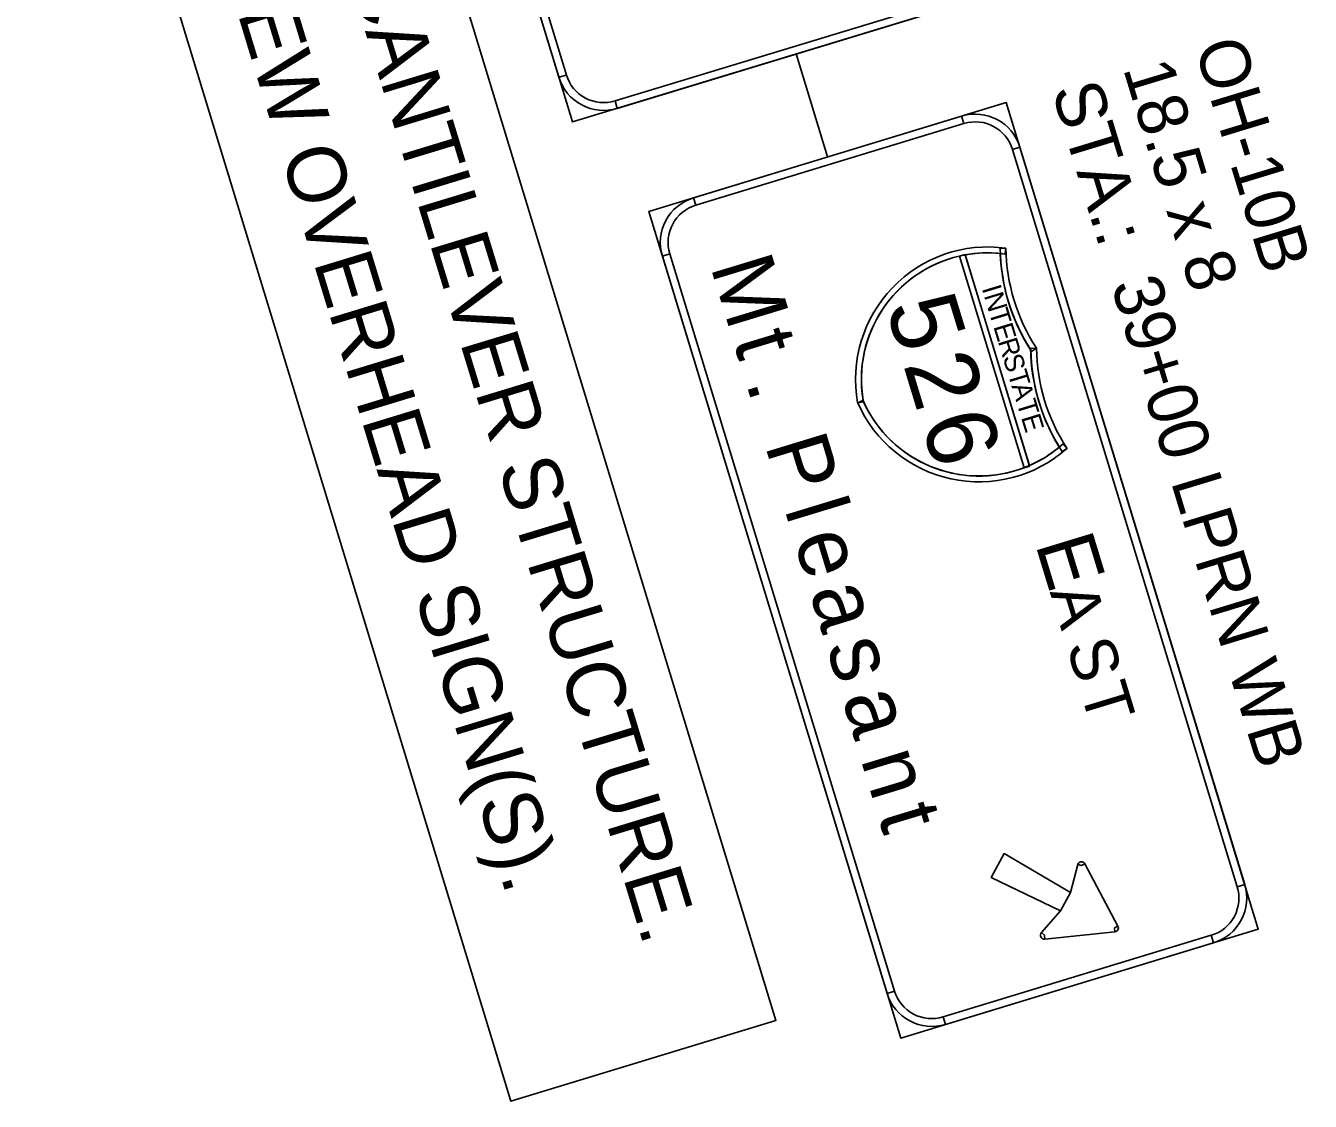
# Model space of a CAD drawing. Extents: x 2338610 to 2351914, y 366540 to 376484.
# Drawn here: x 2348805.7 to 2349063.5, y 367290.3 to 367506.3 of the extents above; entities that cross this region are included whole.
import ezdxf

# ---------------------------------------------------------------- set-up
doc = ezdxf.new("R2010")
doc.units = 0
doc.layers.add('TR PM UNASSIGNED 3', color=7, linetype='Continuous')
doc.layers.add('TR SN EXTRUDED PANEL SIGNS- MOUNTED OVERHEAD', color=7, linetype='Continuous')

msp = doc.modelspace()

# ---------------------------------------------------------------- linework, layer by layer
at = {"layer": 'TR SN EXTRUDED PANEL SIGNS- MOUNTED OVERHEAD'}
for p, q in [((2348966.6, 367479.94), (2348960.3, 367500.64)), ((2348914.19, 367496.4), (2348912.7, 367495.95)), ((2348924.41, 367489.71), (2348923.95, 367491.2)), ((2348993.52, 367488.14), (2348993.98, 367486.65)), ((2349003.73, 367481.45), (2349005.23, 367481.91)), ((2348940.14, 367470.25), (2348939.69, 367471.74)), ((2348933.45, 367460.03), (2348934.94, 367460.49)), ((2349007.13, 367417.99), (2348994.25, 367460.29)), ((2349002.42, 367461.62), (2349001.25, 367461.61)), ((2349002.26, 367460.46), (2349002.42, 367461.62)), ((2348993.09, 367460.05), (2349006.04, 367417.54)), ((2349008.54, 367441.53), (2349007.37, 367441.51)), ((2349007.56, 367440.89), (2349008.54, 367441.53)), ((2348973.72, 367431.06), (2348972.65, 367430.59)), ((2348972.65, 367430.59), (2348973.81, 367430.8)), ((2349014.67, 367421.43), (2349013.89, 367422.31)), ((2349013.68, 367420.79), (2349014.67, 367421.43)), ((2349016.82, 367337.83), (2349017.57, 367337.63)), ((2349017.57, 367337.63), (2349018.26, 367338)), ((2349050.34, 367333.85), (2349048.84, 367333.4)), ((2349010.13, 367323.66), (2349009.54, 367324.18)), ((2349010.21, 367322.88), (2349010.13, 367323.66)), ((2349024.89, 367325.5), (2349024.2, 367325.13)), ((2349024.2, 367325.13), (2349024.28, 367324.35)), ((2349043.64, 367323.64), (2349044.1, 367322.15)), ((2348980.05, 367312.44), (2348978.56, 367311.98)), ((2348990.26, 367305.74), (2348989.81, 367307.24))]:
    msp.add_line(p, q, dxfattribs=at)
for points in [[(2348868.96, 367639.51), (2348915.43, 367486.97), (2349005.16, 367514.31), (2348958.68, 367666.85), (2348868.96, 367639.51), (2348868.96, 367639.51)], [(2348873.19, 367630.99), (2348914.19, 367496.4), (2348912.7, 367495.95), (2348871.69, 367630.54), (2348873.19, 367630.99), (2348873.19, 367630.99)], [(2348858.9, 367626.03), (2348956.25, 367306.52), (2348903.01, 367290.3), (2348805.66, 367609.81)], [(2348923.95, 367491.2), (2348995.73, 367513.07), (2348996.19, 367511.58), (2348924.41, 367489.71), (2348923.95, 367491.2), (2348923.95, 367491.2)], [(2348930.71, 367469.01), (2348981.29, 367303.01), (2349053.07, 367324.88), (2349002.49, 367490.88), (2348930.71, 367469.01), (2348930.71, 367469.01)], [(2348993.98, 367486.65), (2348940.14, 367470.25), (2348939.69, 367471.74), (2348993.52, 367488.14), (2348993.98, 367486.65), (2348993.98, 367486.65)], [(2349048.84, 367333.4), (2349003.73, 367481.45), (2349005.23, 367481.91), (2349050.34, 367333.85), (2349048.84, 367333.4), (2349048.84, 367333.4)], [(2348934.94, 367460.49), (2348980.05, 367312.44), (2348978.56, 367311.98), (2348933.45, 367460.03), (2348934.94, 367460.49), (2348934.94, 367460.49)], [(2348993.09, 367460.05), (2349006.04, 367417.54), (2349007.17, 367417.88), (2348994.22, 367460.39), (2348993.09, 367460.05), (2348993.09, 367460.05)], [(2348999.46, 367335.22), (2349002.03, 367340.05), (2349015.36, 367332.22), (2349013.38, 367328.52), (2348999.46, 367335.22), (2348999.46, 367335.22)], [(2349024.2, 367325.13), (2349024.89, 367325.5), (2349018.26, 367338), (2349017.57, 367337.63), (2349016.82, 367337.83), (2349015.36, 367332.22), (2349013.38, 367328.52), (2349009.54, 367324.18), (2349010.13, 367323.66), (2349010.21, 367322.88), (2349024.28, 367324.35), (2349024.2, 367325.13), (2349024.2, 367325.13)], [(2348989.81, 367307.24), (2349043.64, 367323.64), (2349044.1, 367322.15), (2348990.26, 367305.74), (2348989.81, 367307.24), (2348989.81, 367307.24)]]:
    msp.add_lwpolyline(points, close=True, dxfattribs=at)
for centre, radius, start, end in [((2348921.67, 367498.68), 7.82, 196.9456, 286.9458), ((2348921.67, 367498.68), 9.38, 196.9456, 286.9458), ((2348996.26, 367479.17), 9.38, 16.9457, 106.9454), ((2348996.26, 367479.17), 7.82, 16.9457, 106.9454), ((2348942.42, 367462.77), 9.38, 106.9454, 196.9456), ((2348942.42, 367462.77), 7.82, 106.9454, 196.9456), ((2348998.81, 367435.29), 26.58, 82.1924, 190.1892), ((2348998.81, 367435.29), 26.58, 82.1924, 190.1892), ((2348998.81, 367435.29), 25.4, 82.1924, 190.1892), ((2348998.81, 367435.29), 25.4, 84.4338, 100.3443), ((2349039.94, 367462.08), 38.69, 180.6879, 213.2032), ((2349039.93, 367462.16), 38.69, 182.3489, 212.8314), ((2349039.94, 367462.08), 37.52, 180.6879, 213.2032), ((2349039.94, 367462.08), 37.52, 180.6879, 213.2032), ((2348998.8, 367435.29), 25.4, 102.9811, 189.877), ((2349046.06, 367441.98), 38.69, 180.6879, 213.2032), ((2349046.11, 367441.9), 38.69, 181.0597, 211.5422), ((2349046.06, 367441.98), 37.52, 180.6879, 213.2032), ((2349046.06, 367441.98), 37.52, 180.6879, 213.2032), ((2348996.99, 367441.28), 26.58, 203.7019, 311.6987), ((2348996.99, 367441.28), 26.58, 203.7019, 311.6987), ((2348996.99, 367441.28), 25.4, 203.7019, 311.6987), ((2348996.98, 367441.27), 25.4, 204.0141, 290.9101), ((2348996.99, 367441.28), 25.4, 293.5467, 309.4572), ((2349017.57, 367337.63), 0.782, 27.9259, 165.3916), ((2349041.37, 367331.12), 9.38, 286.9455, 16.9457), ((2349041.37, 367331.12), 7.82, 286.9455, 16.9457), ((2349010.13, 367323.66), 0.782, 138.4993, 275.965), ((2349024.2, 367325.13), 0.782, 275.965, 27.9262), ((2348987.53, 367314.72), 9.38, 196.9456, 286.9458), ((2348987.53, 367314.72), 7.82, 196.9456, 286.9458)]:
    msp.add_arc(centre, radius, start, end, dxfattribs=at)

# ---------------------------------------------------------------- texts
at = {"layer": 'TR PM UNASSIGNED 3'}
for s, p in [('OH-10B', (2349040.22, 367502.13)), ('18.5 x 8', (2349025.87, 367497.75)), ('STA.:  39+00 LPRN WB', (2349011.53, 367493.38))]:
    msp.add_text(s, height=10, rotation=286.9455, dxfattribs=at).set_placement(p)
at = {"layer": 'TR SN EXTRUDED PANEL SIGNS- MOUNTED OVERHEAD'}
for s, height, rotation, p in [('ERECT NEW CANTILEVER STRUCTURE.', 11.7187, 286.9456, (2348841.76, 367610.2)), ('INSTALL NEW OVERHEAD SIGN(S).', 11.7187, 286.9456, (2348825.04, 367584.65)), ('M', 12.51, 286.9455, (2348943.05, 367458)), ('5', 14.07, 286.9455, (2348978.22, 367449.87)), ('I', 3.91, 286.9455, (2348997.52, 367453.57)), ('N', 3.91, 286.9455, (2348997.96, 367452.11)), ('T', 3.91, 286.9455, (2348998.94, 367448.9)), ('t', 12.51, 286.9455, (2348947.58, 367443.14)), ('E', 3.91, 286.9455, (2348999.85, 367445.92)), ('R', 3.91, 286.9455, (2349000.76, 367442.94)), ('2', 14.07, 286.9455, (2348981.74, 367438.3)), ('S', 3.91, 286.9455, (2349001.74, 367439.73)), ('T', 3.91, 286.9455, (2349002.72, 367436.51)), ('.', 12.51, 286.9455, (2348950.17, 367434.66)), ('A', 3.91, 286.9455, (2349003.48, 367434)), ('T', 3.91, 286.9455, (2349004.5, 367430.64)), ('6', 14.07, 286.9455, (2348985.27, 367426.74)), ('E', 3.91, 286.9455, (2349005.41, 367427.66)), ('P', 12.51, 286.9455, (2348953.99, 367422.1)), ('l', 12.51, 286.9455, (2348957.92, 367409.21)), ('e', 12.51, 286.9455, (2348959.73, 367403.27)), ('E', 11.73, 286.9455, (2349008.26, 367402.22)), ('a', 12.51, 286.9455, (2348962.95, 367392.71)), ('A', 9.38, 286.9455, (2349011.19, 367392.6)), ('s', 12.51, 286.9455, (2348966.32, 367381.66)), ('S', 9.38, 286.9455, (2349014.49, 367381.78)), ('T', 9.38, 286.9455, (2349017.23, 367372.78)), ('a', 12.51, 286.9455, (2348969.46, 367371.35)), ('n', 12.51, 286.9455, (2348973.2, 367359.06)), ('t', 12.51, 286.9455, (2348976.59, 367347.93))]:
    msp.add_text(s, height=height, rotation=rotation, dxfattribs=at).set_placement(p)

doc.saveas('drawing.dxf')
